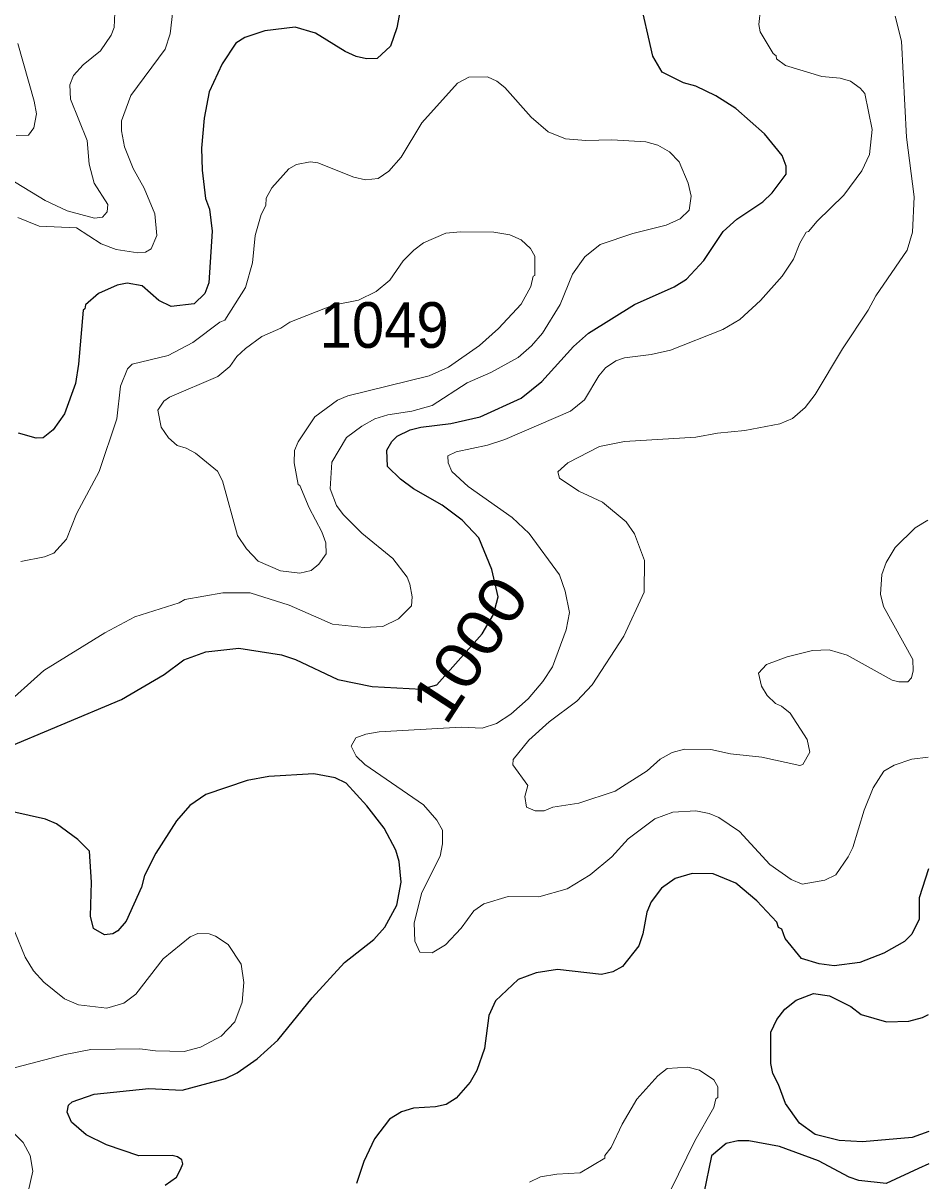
# Model space of a CAD drawing. Extents: x 447.8 to 473.9, y 7733.1 to 7760.8.
# Drawn here: x 472.312 to 473.9, y 7753.711 to 7755.74 of the extents above; entities that cross this region are included whole.
import ezdxf
from ezdxf.enums import TextEntityAlignment as Align

# ---------------------------------------------------------------- set-up
doc = ezdxf.new("R2010")
doc.units = 0
doc.header["$LTSCALE"] = 0.032
doc.layers.add('1', color=7, linetype='Continuous', lineweight=25)
doc.layers.add('2', color=7, linetype='Continuous', lineweight=13)
doc.layers.add('21', color=7, linetype='Continuous')
doc.layers.add('61', color=7, linetype='Continuous')

msp = doc.modelspace()

# ---------------------------------------------------------------- linework, layer by layer
at = {"layer": '1'}
for points in [[(472.98, 7755.8035), (472.9668, 7755.732), (472.9557, 7755.6996)], [(472.2726, 7754.4659), (472.4838, 7754.5547), (472.5587, 7754.5981), (472.5932, 7754.6238), (472.632, 7754.6383), (472.6897, 7754.6446), (472.7644, 7754.6327), (472.789, 7754.6245), (472.8632, 7754.5894), (472.9234, 7754.5773), (473.0098, 7754.5729), (473.0368, 7754.5802), (473.0979, 7754.6488), (473.1165, 7754.6697), (473.1362, 7754.7033), (473.1445, 7754.7345), (473.1334, 7754.7825), (473.1107, 7754.8381), (473.0816, 7754.8689), (473.0465, 7754.8949), (472.996, 7754.9239), (472.9733, 7754.9409), (472.9507, 7754.9632), (472.9491, 7754.9914), (472.9582, 7755.007), (472.9676, 7755.0163), (472.9904, 7755.0269), (473.0087, 7755.0319), (473.0617, 7755.0383), (473.1128, 7755.0498), (473.185, 7755.0825), (473.2208, 7755.112), (473.2767, 7755.1735), (473.3032, 7755.1966), (473.3838, 7755.2468), (473.4533, 7755.2776), (473.4748, 7755.2913), (473.5051, 7755.3239), (473.5388, 7755.3747), (473.5628, 7755.3963), (473.6086, 7755.4268), (473.6252, 7755.4428), (473.6496, 7755.4755), (473.6496, 7755.4895), (473.6426, 7755.5079), (473.6117, 7755.5458), (473.5615, 7755.5902), (473.5259, 7755.6123), (473.4909, 7755.6298), (473.4696, 7755.6351), (473.4321, 7755.6543), (473.4155, 7755.6823), (473.3915, 7755.7881)], [(472.8243, 7755.7226), (472.7887, 7755.7332), (472.7355, 7755.7267), (472.7005, 7755.7147), (472.6844, 7755.7049), (472.6603, 7755.6688), (472.6377, 7755.6197), (472.6293, 7755.5737), (472.6245, 7755.5208), (472.6254, 7755.4823), (472.6315, 7755.4326), (472.6381, 7755.4138), (472.6429, 7755.3751), (472.6372, 7755.285), (472.6304, 7755.2659), (472.6116, 7755.2483), (472.5711, 7755.2435), (472.5495, 7755.2541), (472.5202, 7755.2795), (472.4938, 7755.2843), (472.4762, 7755.2808), (472.4436, 7755.266), (472.4212, 7755.2462), (472.42, 7755.239), (472.4169, 7755.2367), (472.4087, 7755.1424), (472.4032, 7755.1083), (472.384, 7755.0553), (472.3641, 7755.0272), (472.347, 7755.013), (472.3347, 7755.0126), (472.3036, 7755.0212)], [(472.9557, 7755.6996), (472.9325, 7755.6779), (472.9136, 7755.6772), (472.8958, 7755.6813), (472.8762, 7755.6904), (472.8243, 7755.7226)], [(472.859, 7754.4171), (472.8212, 7754.4242), (472.7426, 7754.4195), (472.7045, 7754.4124), (472.6317, 7754.3881), (472.6036, 7754.3689)], [(472.5608, 7753.7035), (472.5805, 7753.7173), (472.5875, 7753.7308), (472.5914, 7753.7409), (472.5896, 7753.7479), (472.5821, 7753.7531), (472.573, 7753.7556), (472.5143, 7753.755), (472.4577, 7753.7738), (472.4223, 7753.7913), (472.3961, 7753.814), (472.3889, 7753.8315), (472.391, 7753.8436), (472.3976, 7753.8494), (472.4361, 7753.8631), (472.5322, 7753.8727), (472.5903, 7753.8696), (472.6666, 7753.8902), (472.6868, 7753.9004), (472.7219, 7753.9246), (472.758, 7753.9576), (472.8182, 7754.0319), (472.8751, 7754.0936), (472.9263, 7754.1338), (472.9456, 7754.1555), (472.9667, 7754.1942), (472.9747, 7754.2341), (472.9708, 7754.2708), (472.965, 7754.2903), (472.9448, 7754.3291), (472.9143, 7754.3683), (472.8778, 7754.4077), (472.859, 7754.4171)], [(472.6036, 7754.3689), (472.5806, 7754.3419), (472.5442, 7754.2853), (472.5246, 7754.2462), (472.5193, 7754.2259), (472.4921, 7754.1661), (472.4777, 7754.1493), (472.4691, 7754.1436), (472.4541, 7754.1421), (472.4347, 7754.1534), (472.4297, 7754.1749), (472.4312, 7754.2341), (472.4278, 7754.2888), (472.4074, 7754.3094), (472.3703, 7754.3368), (472.3508, 7754.3449), (472.2937, 7754.3576)], [(473.8989, 7754.258), (473.883, 7754.207), (473.8829, 7754.1694), (473.8698, 7754.1434), (473.8569, 7754.1306), (473.8209, 7754.1099), (473.7787, 7754.0937), (473.7334, 7754.0878), (473.7072, 7754.0912), (473.6763, 7754.1004), (473.6477, 7754.1357), (473.6417, 7754.152), (473.6362, 7754.155), (473.6332, 7754.1643), (473.5981, 7754.2017), (473.5611, 7754.2328), (473.5215, 7754.2487), (473.4845, 7754.2494), (473.4548, 7754.2406), (473.4309, 7754.2237), (473.4128, 7754.2), (473.4052, 7754.1816), (473.3981, 7754.1436), (473.391, 7754.1229), (473.3623, 7754.0866), (473.3453, 7754.0773), (473.3258, 7754.0724), (473.2488, 7754.0811), (473.2111, 7754.0757), (473.1798, 7754.0638), (473.1399, 7754.0266), (473.128, 7754.0006), (473.1207, 7753.9428), (473.1069, 7753.9041), (473.0954, 7753.8839), (473.0707, 7753.8557), (473.0532, 7753.8447), (473.0344, 7753.8407), (472.9959, 7753.8383), (472.9751, 7753.8321), (472.9541, 7753.8192), (472.9279, 7753.7844), (472.9088, 7753.745), (472.8961, 7753.7065)], [(473.8996, 7753.7973), (473.8705, 7753.7871), (473.7831, 7753.779), (473.7426, 7753.7816), (473.7006, 7753.7919), (473.6728, 7753.8121), (473.6481, 7753.8463), (473.6362, 7753.8796), (473.6261, 7753.8991), (473.6224, 7753.9165), (473.6226, 7753.9715), (473.6329, 7753.9937), (473.647, 7754.0119), (473.6673, 7754.0274), (473.6977, 7754.0393), (473.7254, 7754.0353), (473.7631, 7754.0164), (473.7812, 7754.0026), (473.8257, 7753.9898), (473.8648, 7753.9906), (473.8884, 7753.997), (473.8993, 7754.0027)], [(473.8997, 7753.741), (473.8814, 7753.7325), (473.8247, 7753.7062), (473.7771, 7753.7115), (473.76, 7753.7175), (473.706, 7753.7459), (473.6376, 7753.7711), (473.5839, 7753.7813), (473.5646, 7753.7813), (473.5442, 7753.7765), (473.5186, 7753.7548), (473.5053, 7753.6891)]]:
    msp.add_lwpolyline(points, dxfattribs=at)
at = {"layer": '2'}
for points in [[(473.6266, 7755.6868), (473.6039, 7755.7247), (473.6017, 7755.7376), (473.6047, 7755.7645), (473.6199, 7755.7982), (473.624, 7755.8387)], [(472.5789, 7755.8027), (472.5692, 7755.7211), (472.5609, 7755.6944), (472.5002, 7755.6129), (472.4842, 7755.5686), (472.4842, 7755.5513), (472.4895, 7755.5233), (472.5048, 7755.485), (472.5236, 7755.4507), (472.5427, 7755.4058), (472.5463, 7755.368), (472.5359, 7755.3443), (472.5264, 7755.3383), (472.5127, 7755.3374), (472.4749, 7755.3433), (472.4486, 7755.3534), (472.4054, 7755.3813), (472.3395, 7755.3844), (472.3024, 7755.3993)], [(472.4728, 7755.7707), (472.4714, 7755.7322), (472.4661, 7755.7189), (472.4471, 7755.6915), (472.417, 7755.6668), (472.4, 7755.6482), (472.3936, 7755.6319), (472.3944, 7755.6068), (472.4236, 7755.5343), (472.4272, 7755.4927), (472.4359, 7755.4595), (472.4601, 7755.422), (472.4591, 7755.409), (472.451, 7755.3997)], [(473.8404, 7755.7524), (473.8515, 7755.7082), (473.8603, 7755.5404), (473.8741, 7755.4356), (473.8708, 7755.3738), (473.8614, 7755.342), (473.8066, 7755.2623), (473.7935, 7755.2368), (473.7484, 7755.1692), (473.7003, 7755.089), (473.6831, 7755.0661), (473.6608, 7755.0471), (473.6382, 7755.0378), (473.5772, 7755.0262), (473.5291, 7755.0214), (473.4912, 7755.0143), (473.3662, 7755.007), (473.3223, 7754.9981), (473.2668, 7754.9695), (473.2491, 7754.9538), (473.2523, 7754.9427), (473.286, 7754.9195), (473.3276, 7754.9002), (473.3689, 7754.8662), (473.3835, 7754.845), (473.4011, 7754.7982), (473.4004, 7754.7428), (473.365, 7754.6656), (473.3091, 7754.58), (473.2823, 7754.5514), (473.2342, 7754.5154), (473.1983, 7754.4835), (473.1706, 7754.4491), (473.1703, 7754.4399), (473.1967, 7754.4041), (473.1912, 7754.3846), (473.1944, 7754.3659), (473.2094, 7754.3595), (473.2253, 7754.3593), (473.2401, 7754.3657), (473.2859, 7754.3726), (473.3495, 7754.3936), (473.4057, 7754.4294), (473.4287, 7754.45), (473.4498, 7754.4618), (473.471, 7754.4674), (473.5172, 7754.4667), (473.552, 7754.4592), (473.607, 7754.4537), (473.6734, 7754.4387), (473.6787, 7754.4404), (473.6912, 7754.462), (473.6864, 7754.4846), (473.6568, 7754.5308), (473.6413, 7754.5429), (473.6308, 7754.5475), (473.6163, 7754.5617), (473.6061, 7754.578), (473.6012, 7754.6006), (473.6148, 7754.6156), (473.6512, 7754.6294), (473.6954, 7754.6405), (473.725, 7754.6414), (473.7567, 7754.632), (473.8353, 7754.5887), (473.8468, 7754.5854), (473.8629, 7754.5857), (473.869, 7754.5924), (473.8724, 7754.605), (473.8717, 7754.6247), (473.8201, 7754.7175), (473.8148, 7754.7389), (473.8173, 7754.7736), (473.8249, 7754.7947), (473.8404, 7754.821), (473.8759, 7754.8552), (473.898, 7754.8686)], [(472.2996, 7755.5428), (472.3209, 7755.5438), (472.3305, 7755.5567), (472.335, 7755.5809), (472.3311, 7755.603), (472.3021, 7755.7043)], [(473.8986, 7754.4533), (473.8699, 7754.4499), (473.8386, 7754.4393), (473.8209, 7754.4288), (473.8019, 7754.3995), (473.7863, 7754.3603), (473.7666, 7754.2952), (473.7585, 7754.2789), (473.7364, 7754.2473), (473.7175, 7754.2377), (473.6777, 7754.2311), (473.6583, 7754.2388), (473.6211, 7754.2652), (473.5676, 7754.3234), (473.5313, 7754.3479), (473.5146, 7754.3546), (473.4912, 7754.3593), (473.4508, 7754.3569), (473.4194, 7754.3451), (473.3722, 7754.3102), (473.3437, 7754.2786), (473.3058, 7754.2475), (473.2656, 7754.2225), (473.2158, 7754.2087), (473.1623, 7754.2094), (473.1193, 7754.1967), (473.1018, 7754.1842), (473.0795, 7754.1539), (473.0524, 7754.1245), (473.029, 7754.1103), (473.0072, 7754.1116), (472.9986, 7754.1311), (472.9972, 7754.1629), (473.0105, 7754.216), (473.0428, 7754.2801), (473.0468, 7754.3013), (473.0467, 7754.3258), (473.0372, 7754.3432), (473.0138, 7754.3699), (472.9106, 7754.4404), (472.8958, 7754.455), (472.8865, 7754.4726), (472.895, 7754.4876), (472.9123, 7754.4939), (472.9359, 7754.4979), (473.0799, 7754.506), (473.1165, 7754.5044), (473.1417, 7754.5126), (473.1669, 7754.5291), (473.1971, 7754.556), (473.2227, 7754.5859), (473.2395, 7754.6116), (473.2637, 7754.6766), (473.2696, 7754.7071), (473.2622, 7754.7447), (473.252, 7754.7729), (473.1989, 7754.8453), (473.169, 7754.8737), (473.0917, 7754.9276), (473.0631, 7754.954), (473.0566, 7754.9694), (473.056, 7754.9816), (473.0706, 7754.9889), (473.1257, 7755.0002), (473.1562, 7755.0102), (473.2716, 7755.06), (473.2958, 7755.0797), (473.3209, 7755.1221), (473.3328, 7755.1357), (473.3507, 7755.148), (473.3659, 7755.1536), (473.4125, 7755.159), (473.4468, 7755.1668), (473.5387, 7755.2032), (473.5682, 7755.2204), (473.6045, 7755.2536), (473.6427, 7755.2965), (473.6626, 7755.3263), (473.6736, 7755.3545), (473.6848, 7755.3738), (473.6888, 7755.3749), (473.7036, 7755.3928), (473.7509, 7755.4385), (473.7823, 7755.4809), (473.7954, 7755.51), (473.8003, 7755.5533), (473.7873, 7755.6164), (473.7795, 7755.6258), (473.7626, 7755.6385), (473.7439, 7755.6434), (473.7121, 7755.6466), (473.6484, 7755.6657), (473.6324, 7755.6776), (473.6317, 7755.6829), (473.6266, 7755.6868)], [(472.3073, 7754.7962), (472.3488, 7754.8047), (472.3656, 7754.8109), (472.3879, 7754.8357), (472.4053, 7754.8797), (472.4447, 7754.954), (472.476, 7755.0467), (472.4823, 7755.1037), (472.4947, 7755.1338), (472.5027, 7755.1424), (472.5658, 7755.1574), (472.6093, 7755.18), (472.6563, 7755.216), (472.6653, 7755.2195), (472.7012, 7755.2764), (472.7139, 7755.3196), (472.7183, 7755.3677), (472.7292, 7755.4044), (472.7372, 7755.4203), (472.7379, 7755.433), (472.7474, 7755.4514), (472.7773, 7755.4845), (472.7911, 7755.4921), (472.8151, 7755.4967), (472.8283, 7755.4952), (472.8915, 7755.4699), (472.9119, 7755.4655), (472.9341, 7755.4676), (472.9527, 7755.4804), (472.9747, 7755.5053), (473.0108, 7755.5654), (473.0731, 7755.635), (473.0933, 7755.645), (473.1259, 7755.646), (473.1422, 7755.6383), (473.1561, 7755.6272), (473.2025, 7755.5751), (473.2323, 7755.5493), (473.2627, 7755.5374), (473.298, 7755.534), (473.344, 7755.5353), (473.4034, 7755.5319), (473.4246, 7755.5259), (473.4451, 7755.5144), (473.4616, 7755.4969), (473.4779, 7755.4597), (473.4829, 7755.4366), (473.4797, 7755.4119), (473.4634, 7755.3972), (473.4391, 7755.3857)], [(472.451, 7755.3997), (472.4365, 7755.3982), (472.3889, 7755.4112), (472.3505, 7755.429), (472.2075, 7755.5158), (472.134, 7755.5772)], [(473.4391, 7755.3857), (473.3806, 7755.371), (473.3233, 7755.3519), (473.2964, 7755.3302), (473.2746, 7755.3001), (473.2533, 7755.2468)], [(473.2533, 7755.2468), (473.222, 7755.1968), (473.2029, 7755.1743), (473.1797, 7755.1538), (473.1317, 7755.1279), (473.09, 7755.1094), (473.0286, 7755.0701), (472.9929, 7755.06), (472.9513, 7755.0536), (472.9283, 7755.0462), (472.9052, 7755.0338), (472.8788, 7755.0136), (472.853, 7754.9705), (472.8497, 7754.9237), (472.8612, 7754.8948), (472.8729, 7754.8787), (472.9055, 7754.8461), (472.9601, 7754.8019), (472.9848, 7754.7688), (472.9899, 7754.7569), (472.9939, 7754.7345), (472.9923, 7754.7188), (472.9697, 7754.6958), (472.9422, 7754.6824), (472.9095, 7754.6808), (472.8539, 7754.6864), (472.7778, 7754.7199), (472.7099, 7754.7417), (472.6618, 7754.7416), (472.595, 7754.7297), (472.5854, 7754.7242), (472.5076, 7754.6996), (472.4547, 7754.6715), (472.3481, 7754.6055), (472.2736, 7754.5389)], [(472.2972, 7754.1471), (472.3149, 7754.103), (472.3299, 7754.0789), (472.348, 7754.0591), (472.3844, 7754.0297), (472.4088, 7754.0194), (472.4586, 7754.0134), (472.4883, 7754.0223), (472.509, 7754.0379), (472.5569, 7754.1002), (472.6045, 7754.1385), (472.6181, 7754.1443), (472.6377, 7754.1436), (472.6486, 7754.1399), (472.6711, 7754.125), (472.6941, 7754.0904), (472.6988, 7754.0586), (472.6957, 7754.0242), (472.683, 7753.9895), (472.6589, 7753.9642), (472.6227, 7753.9451), (472.5938, 7753.9377), (472.5439, 7753.9385), (472.5162, 7753.9424), (472.43, 7753.9409), (472.3854, 7753.9322), (472.262, 7753.9002)], [(473.1994, 7753.7086), (473.2187, 7753.7181), (473.2473, 7753.7228), (473.2885, 7753.7251), (473.3318, 7753.7507), (473.3318, 7753.7553), (473.3426, 7753.7694), (473.362, 7753.8105), (473.3876, 7753.8543), (473.4245, 7753.8951), (473.4406, 7753.9076), (473.4772, 7753.9103), (473.4976, 7753.9047), (473.5228, 7753.8879), (473.5295, 7753.8754), (473.5294, 7753.8571), (473.5263, 7753.8548), (473.5229, 7753.8396), (473.4895, 7753.7808), (473.4468, 7753.694)], [(472.2939, 7753.7959), (472.3118, 7753.7781), (472.3238, 7753.7554), (472.3285, 7753.7276), (472.3202, 7753.6918)]]:
    msp.add_lwpolyline(points, dxfattribs=at)
msp.add_lwpolyline([(473.1367, 7755.3739), (473.1649, 7755.3687), (473.1847, 7755.3604), (473.2013, 7755.3452), (473.2087, 7755.3313), (473.2087, 7755.2976), (473.206, 7755.2965), (473.2019, 7755.2786), (473.1849, 7755.2477), (473.1451, 7755.2046), (473.1119, 7755.1748), (473.0575, 7755.1372), (473.0237, 7755.1218), (472.8811, 7755.0869), (472.8626, 7755.0791), (472.8232, 7755.0501), (472.7937, 7755.0064), (472.7872, 7754.9911), (472.7867, 7754.9696), (472.7936, 7754.9312), (472.7966, 7754.9299), (472.8129, 7754.8906), (472.8351, 7754.8485), (472.8424, 7754.829), (472.8431, 7754.8099), (472.8298, 7754.7915), (472.8169, 7754.7805), (472.797, 7754.7762), (472.7626, 7754.7799), (472.7238, 7754.7968), (472.7034, 7754.8186), (472.6876, 7754.8422), (472.6613, 7754.938), (472.6526, 7754.955), (472.6138, 7754.986), (472.5973, 7754.9953), (472.5817, 7754.9998), (472.5662, 7755.0132), (472.5534, 7755.032), (472.5476, 7755.0618), (472.5581, 7755.0776), (472.5681, 7755.0842), (472.6529, 7755.1204), (472.6739, 7755.1382), (472.6865, 7755.1555), (472.7013, 7755.1697), (472.7303, 7755.1905), (472.7634, 7755.2051), (472.779, 7755.2159), (472.8552, 7755.2455), (472.8994, 7755.2543), (472.9308, 7755.2697), (472.9544, 7755.2897), (472.9782, 7755.3231), (472.9966, 7755.3423), (473.0135, 7755.355), (473.0529, 7755.3717), (473.0784, 7755.3742)], close=True, dxfattribs=at)

# ---------------------------------------------------------------- texts
at = {"layer": '21', "width": 0.95}
msp.add_text('1049', height=0.08, dxfattribs=at).set_placement((472.8316, 7755.1709))
at = {"layer": '61', "width": 1.15}
msp.add_text('1000', height=0.08, rotation=56.859, dxfattribs=at).set_placement((473.1275, 7754.621), align=Align.CENTER)

doc.saveas('drawing.dxf')
